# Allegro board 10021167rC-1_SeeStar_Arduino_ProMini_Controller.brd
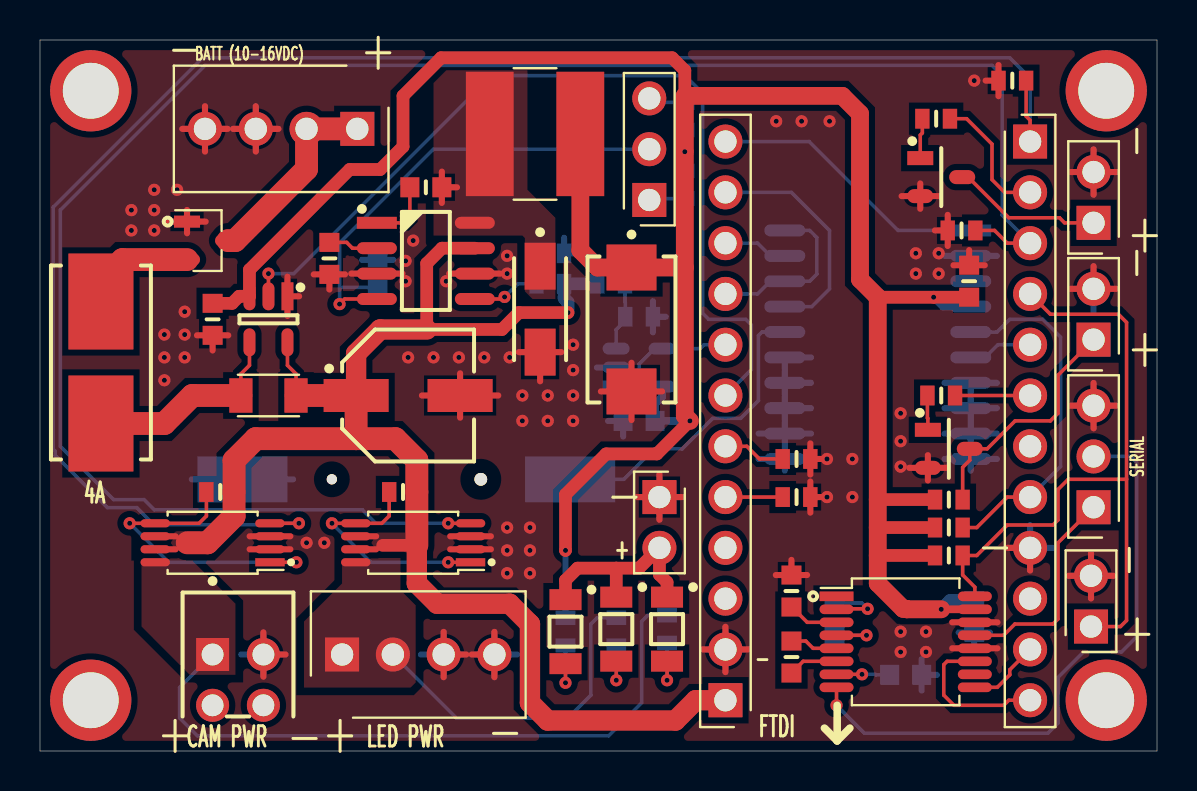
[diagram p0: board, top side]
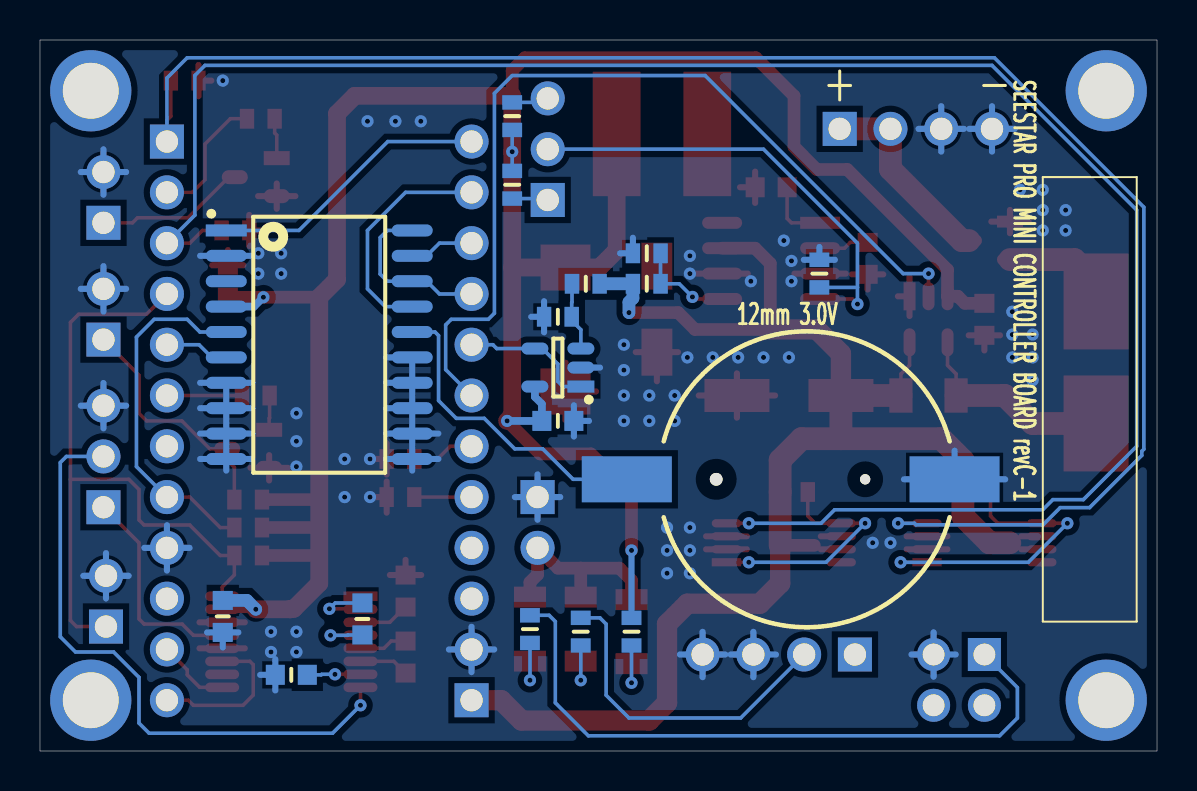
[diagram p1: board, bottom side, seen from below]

Outline 55.88 x 35.56 mm; copper layers: TOP, BOTTOM. Coordinates in mm from the lower left corner of the outline.
Outline path: 0,35.56 0,0 55.88,0 55.88,35.56 0,35.56

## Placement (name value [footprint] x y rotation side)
BT1  S8411-45R  [HARWIN_S8411-45R]  18.33 13.59 270 bottom
C1  0.1uF  [CAPC1608X90N]  19.3 28.19 0 top
C2  47uF  [CAPAE660X800N]  18.41 17.78 0 top
C3  68uF  [CAPMP7343X310N]  29.59 21.08 270 top
C4  0.10uF  [CAPC1608X87N]  8.64 21.59 270 top
C5  0.1uF  [CAPC1608X90N]  14.48 24.64 270 top
C6  0.22uF  [CAPC1608X95N]  46.74 6.73 270 bottom
C7  1.0uF  [CAPC1608X90N]  37.59 4.7 270 top
C8  0.22uF  [CAPC1608X95N]  39.75 6.6 270 bottom
C9  1.0uF  [CAPC1608X90N]  43.31 3.81 0 bottom
C10  1.0uF  [CAPC1608X90N]  37.59 8 90 top
C11  0.10uF  [CAPC1608X87N]  46.48 23.5 90 top
C12  0.10uF  [CAPC1608X87N]  29.97 16.51 180 bottom
D1  B340A-13-F  [DIOM5226X230N]  25.02 22.1 270 top
D2  LTST-C150TBKT  [LED_LTST-C150XXX]  31.37 6.1 270 top
D3  LTST-C150KRKT  [LED_LTST-C150XXX]  28.83 6.1 270 top
D4  LTST-C150KGKT  [LED_LTST-C150XXX]  26.29 5.97 270 top
F1  0154004.DRT  [FUSM9750X381N]  3.05 19.43 270 top
J1  1725672  [PHOENIX_1725672]  12.06 31.11 180 top
J2  TSW-103-14-T-S  [SAMTEC_TSW-103-14]  30.48 27.56 90 top
J3  1725656  [PHOENIX_1725656]  8.64 4.83 0 top
J4  TSW-102-14-T-S  [SAMTEC_TSW-102-14]  52.58 6.22 90 top
J5  SSW-103-01-T-S  [SAMTEC_SSW-103-XX-XXX-S-X]  52.7 14.73 90 top
J6  SSW-112-01-T-S  [SAMTEC_SSW-112-XX-XXX-S-X]  34.29 16.51 90 top
J7  SSW-112-01-T-S  [SAMTEC_SSW-112-XX-XXX-S-X]  49.53 16.51 270 top
J8  1725672  [PHOENIX_1725672]  18.92 4.83 0 top
J9  TSW-102-14-T-S  [SAMTEC_TSW-102-14]  30.99 12.7 270 top
J10  SSW-102-01-T-S  [SAMTEC_SSW-102-XX-XXX-S-X]  52.7 27.69 90 top
J11  SSW-102-01-T-S  [SAMTEC_SSW-102-XX-XXX-S-X]  52.7 21.84 90 top
L1  100uH  [IND_SRN6045]  24.77 30.86 0 top
NOREF  -  [unnamed]  2.54 33.02 0 top
NOREF#2  -  [#2]  0 0 0 top
NOREF#3  -  [#2]  0 0 0 top
NOREF#4  -  [#2]  50.8 33.02 180 top
NOREF#5  -  [#2]  -50.8 -76.2 0 top
NOREF#6  -  [#2]  0 0 0 top
NOREF#7  -  [unnamed]  2.54 2.54 0 top
NOREF#8  -  [#2]  55.88 0 90 top
NOREF#9  -  [#2]  55.88 0 90 top
NOREF#10  -  [#2]  55.88 0 90 top
NOREF#11  -  [unnamed]  53.34 33.02 0 top
NOREF#12  -  [unnamed]  53.34 2.54 0 top
NOREF#13  -  [#2]  249.81 111.38 0 top
Q1  SI2369DS-T1-GE3  [SOT95P237X112-3L20N_132]  8.38 25.53 270 top
Q2  SI6562CDQ-T1-GE3  [SOP65P640X120-8L30N]  8.64 10.41 90 top
Q3  SI6562CDQ-T1-GE3  [SOP65P640X120-8L30N]  18.67 10.41 90 top
Q4  MMBT3904  [SOT95P240X130-3N_132]  45.09 28.7 0 top
Q5  MMBT3904  [SOT95P240X130-3N_132]  45.47 15.11 0 top
R1  0.02  [RESC3015X65N]  11.43 17.78 0 top
R2  1.00M  [RESC1608X50N]  25.53 23.37 180 bottom
R3  121.0K  [RESC1608X50N]  28.57 23.37 0 bottom
R4  22.6K  [RESC1608X50N]  32.26 31.75 90 bottom
R5  41.2K  [RESC1608X50N]  32.26 28.32 270 bottom
R6  28.0K  [RESC1608X50N]  29.97 21.72 0 bottom
R7  383.0K  [RESC1608X50N]  25.53 24.89 0 bottom
R8  13.3K  [RESC1608X50N]  16.89 23.88 90 bottom
R9  100.0K  [RESC1608X50N]  9.02 12.95 0 top
R10  100.0K  [RESC1608X50N]  45.47 9.78 0 top
R11  100.0K  [RESC1608X50N]  48.64 33.53 180 top
R12  100.0K  [RESC1608X50N]  18.16 12.95 0 top
R13  100.0K  [RESC1608X50N]  46.1 26.04 180 top
R14  1.69K  [RESC1608X50N]  31.37 6.1 270 bottom
R15  1.69K  [RESC1608X50N]  28.83 5.97 270 bottom
R16  130  [RESC1608X50N]  26.29 5.97 270 bottom
R17  10.0K  [RESC1608X50N]  44.83 31.62 180 top
R18  100.0K  [RESC1608X50N]  45.47 11.18 0 top
R19  100.0K  [RESC1608X50N]  45.47 12.57 0 top
R20  0.0  [RESC1608X50N]  37.85 12.7 0 top
R21  0.0  [RESC1608X50N]  37.85 14.61 0 top
R22  10.0K  [RESC1608X50N]  45.09 17.78 180 top
U1  MAX5035DASA+  [SOIC127P600X175-8N]  19.3 24.51 0 top
U2  MAX4372FEUK+T  [SOT95P280X145-5N]  11.43 21.59 270 top
U3  AD8603AUJZ  [SOT95P280X100-5N]  29.97 19.18 0 bottom
U4  MAX3227EAAE+  [SOP65P777X199-16L32N]  43.31 5.46 270 top
U5  DS3234S#  [SOIC127P1032X265-20N]  41.91 20.32 180 bottom

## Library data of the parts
BT1 = BATTERY
C1 C4-C12 = CAP
C2 C3 = CAP_P
D1 = DIODE_SCHOTTKY
D2-D4 = LED
F1 = FUSEHOLDER_2T_2PIN
J1 J8 = CON4
J2 = HEADER 3_SYM-MOD1
J3 J10 J11 = CON2
J4 J9 = HEADER 2_SYM-MOD1
J5 = CON3
J6 J7 = CON12
L1 = IND
Q1 = MOSFET_I_EP_GSD
Q2 Q3 = MOSFET_I_PN_DSSGGSSD_SYM-MOD1
Q4 Q5 = BJT_NPN_BEC
R1-R22 = RES
U1 = MAX5035
U2 = MAX4372xEUK-T_SYM-MOD1
U3 = AD8603
U4 = MAX3227E
U5 = DS3234Sx

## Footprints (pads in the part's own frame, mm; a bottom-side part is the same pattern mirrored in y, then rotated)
CAPAE660X800N
  rect 3.251x1.651 smd: 1(-2.601,0) 2(2.601,0)
CAPC1608X87N
  rect 0.95x1.001 smd: 1(-0.8,0) 2(0.8,0)
CAPC1608X90N
  rect 0.95x1.001 smd: 1(-0.8,0) 2(0.8,0)
CAPC1608X95N
  rect 0.95x1.001 smd: 1(-0.8,0) 2(0.8,0)
CAPMP7343X310N
  rect 2.301x2.499 smd: 1(-3.099,0) 2(3.099,0)
DIOM5226X230N
  rect 2.349x1.549 smd: A(2.149,0) C(-2.149,0)
FUSM9750X381N
  rect 4.801x3.251 smd: 1(-3.051,0) 2(3.051,0)
HARWIN_S8411-45R
  round 0.635 hole 1.27 unplated: (0,-3.726)
  round 0.508 hole 1.016 unplated: (0,3.726)
  rect 2.301x4.501 smd: 1(0,-8.199) 2(0,8.199)
IND_SRN6045
  rect 2.39x6.22 smd: 1(-2.266,0) 2(2.266,0)
LED_LTST-C150XXX
  rect 1.049x1.6 smd: A(1.6,0) C(-1.6,0)
PHOENIX_1725656
  round 1.651 hole 1.092: (0,-2.54) (2.54,-2.54) 2(2.54,0)
  rect 1.651x1.651 hole 1.092: 1(0,0)
PHOENIX_1725672
  rect 1.702x1.702 hole 1.118: 1(-3.81,0)
  round 1.702 hole 1.118: 2(-1.27,0) 3(1.27,0) 4(3.81,0)
RESC1608X50N
  rect 0.719x0.991 smd: 1(-0.691,0) 2(0.691,0)
RESC3015X65N
  rect 1.161x1.72 smd: 1(-1.379,0) 2(1.379,0)
SAMTEC_SSW-102-XX-XXX-S-X
  rect 1.702x1.702 hole 1.118: 1(-1.27,0)
  round 1.702 hole 1.118: 2(1.27,0)
SAMTEC_SSW-103-XX-XXX-S-X
  rect 1.702x1.702 hole 1.118: 1(-2.54,0)
  round 1.702 hole 1.118: 2(0,0) 3(2.54,0)
SAMTEC_SSW-112-XX-XXX-S-X
  rect 1.702x1.702 hole 1.118: 1(-13.97,0)
  round 1.702 hole 1.118: 2(-11.43,0) 3(-8.89,0) 4(-6.35,0) 5(-3.81,0) 6(-1.27,0) 7(1.27,0) 8(3.81,0) 9(6.35,0) 10(8.89,0) 11(11.43,0) 12(13.97,0)
SAMTEC_TSW-102-14
  rect 1.702x1.702 hole 1.118: 1(0,0)
  round 1.702 hole 1.118: 2(2.54,0)
SAMTEC_TSW-103-14
  rect 1.702x1.702 hole 1.118: 1(0,0)
  round 1.702 hole 1.118: 2(2.54,0) 3(5.08,0)
SOIC127P600X175-8N
  rect 1.999x0.599 smd: 1(-2.451,1.905)
  oval 1.999x0.599 smd: 2(-2.451,0.635) 3(-2.451,-0.635) 4(-2.451,-1.905) 5(2.451,-1.905) 6(2.451,-0.635) 7(2.451,0.635) 8(2.451,1.905)
SOIC127P1032X265-20N
  rect 2.05x0.599 smd: 1(-4.651,5.715)
  oval 2.05x0.599 smd: 2(-4.651,4.445) 3(-4.651,3.175) 4(-4.651,1.905) 5(-4.651,0.635) 6(-4.651,-0.635) 7(-4.651,-1.905) 8(-4.651,-3.175) 9(-4.651,-4.445) 10(-4.651,-5.715) 11(4.651,-5.715) 12(4.651,-4.445) 13(4.651,-3.175) 14(4.651,-1.905) 15(4.651,-0.635) 16(4.651,0.635) 17(4.651,1.905) 18(4.651,3.175) 19(4.651,4.445) 20(4.651,5.715)
SOP65P640X120-8L30N
  rect 0.409x1.471 smd: 1(-0.975,-2.87)
  oval 0.409x1.471 smd: 2(-0.325,-2.87) 3(0.325,-2.87) 4(0.975,-2.87) 5(0.975,2.87) 6(0.325,2.87) 7(-0.325,2.87) 8(-0.975,2.87)
SOP65P777X199-16L32N
  rect 0.48x1.699 smd: 1(-2.276,-3.459)
  oval 0.48x1.699 smd: 2(-1.626,-3.459) 3(-0.975,-3.459) 4(-0.325,-3.459) 5(0.325,-3.459) 6(0.975,-3.459) 7(1.626,-3.459) 8(2.276,-3.459) 9(2.276,3.459) 10(1.626,3.459) 11(0.975,3.459) 12(0.325,3.459) 13(-0.325,3.459) 14(-0.975,3.459) 15(-1.626,3.459) 16(-2.276,3.459)
SOT95P237X112-3L20N_132
  rect 0.599x1.3 smd: 1(-0.95,-1.026)
  oval 0.599x1.3 smd: 2(0.95,-1.026) 3(0,1.026)
SOT95P240X130-3N_132
  rect 1.3x0.701 smd: 1(-1.049,0.95)
  oval 1.3x0.701 smd: 2(-1.049,-0.95) 3(1.049,0)
SOT95P280X100-5N
  rect 1.349x0.599 smd: 1(-1.151,0.95)
  oval 1.349x0.599 smd: 2(-1.151,0) 3(-1.151,-0.95) 4(1.151,-0.95) 5(1.151,0.95)
SOT95P280X145-5N
  rect 1.4x0.599 smd: 1(-1.151,0.95)
  oval 1.4x0.599 smd: 2(-1.151,0) 3(-1.151,-0.95) 4(1.151,-0.95) 5(1.151,0.95)
unnamed
  round 4.064 hole 2.794: (0,0)

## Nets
GND_SIGNAL: BT1.2(-) C2.2 C3.2 C4.2 C5.2 C6.2 C9.2 C10.2 C11.2 C12.2 D1.A J1.3 J1.4 J3.2 J4.2 J5.3 J6.2 J7.9 J8.3 J8.4 J9.1 J10.2 J11.2 Q1.1(G) Q2.2(S1B) Q2.3(S1A) Q3.2(S1B) Q3.3(S1A) Q4.2(E) Q5.2(E) R6.2 R7.2 R8.2 R11.2 R13.2 R20.2 R21.2 U1.3(SGND) U1.6(GND) U2.1(GND) U3.2(V-) U4.12(FORCEON) U4.14(GND) U5.2(NC2) U5.7(NC7) U5.8(NC8) U5.9(NC9) U5.10(NC10) U5.11(NC11) U5.12(NC12) U5.13(NC13) U5.14(NC14) U5.15(GND)
VDD: C3.1 C4.1 C6.1 C11.1 C12.1 L1.2 R4.1 R5.1 R10.1 R16.1 R18.1 R19.1 U2.3(VCC) U3.5(V+) U4.15(VCC) U5.4(VCC)
BATT: C2.1 J6.1 Q2.6(S2B) Q2.7(D2A) Q3.6(S2B) Q3.7(D2A) R1.2 R2.1 R3.1 R9.2 R12.2 U1.7(VIN) U2.5(RS-)
BATT_CURR: J6.7 U2.2(OUT)
BATT_VOLT: J6.8 U3.1(OUT) U3.4(IN-)
CAM_ON: J7.2 R17.1
CAM_POWER: J7.1 Q2.4(G1) R11.1
LED_ON: J7.6 R22.1
LED_POWER: J7.3 Q3.4(G1) R13.1
MISO: J6.10 U5.19(DOUT)
MOSI: J6.11 U5.17(DIN)
RTC_INT: J7.8 R18.2 U5.5(I\N\T\/SQW)
RTC_RESET: J7.5 U5.6(R\S\T\)
RTC_SS: J6.12 U5.1(C\S\)
RXD: J7.11 U4.9(R1_OUT)
SCK: J6.9 U5.18(SCLK_1) U5.20(SCLK_0)
TXD: J7.12 U4.11(T1_IN)
UART_SHDN: J4.1 J7.4 R10.2 U4.16(\\F\O\R\C\E\O\F\F)
N15180757: J11.1 Q5.3(C) R19.2
N15180795: Q5.1(B) R22.2
N15180973: J1.1 J1.2 Q1.3(D)
N15180993: J8.1 J8.2 Q3.8(D2) R15.1
N15181069: J6.6 R21.1
N15181133: J6.5 R20.1
N15181323: F1.1 Q1.2(S)
N15181327: F1.2 R1.1 U2.4(RS+)
N15181383: D4.A R16.2
N15181515: R3.2 R6.1 U3.3(IN+)
N15181811: J10.1 Q4.3(C)
N15181975: BT1.1(+) U5.16(VBAT)
N15182163: Q4.1(B) R17.2
N15182191: J5.1 U4.13(T1_OUT)
N15182195: J5.2 U4.8(R1_IN)
N15182295: D2.A R14.2
N15182299: D3.A R15.2
N15182387: J3.1 Q2.8(D2) R14.1
N15182531: D2.C D3.C D4.C J9.2
N15183153: R2.2 R7.1 U1.5(ON/\O\F\F\)
N15183237: C1.2 D1.C L1.1 U1.8(LX)
N15183261: J2.2 R8.1 U1.4(FB)
N15183297: C5.1 U1.2(VD)
N15183305: C1.1 U1.1(BST)
N15187989: Q3.1(D1) Q3.5(G2) R12.1
N15190814: Q2.1(D1) Q2.5(G2) R9.1
N15195894: J2.3 R4.2
N15201520: C7.2 U4.6(C2-)
N15201524: C7.1 U4.5(C2+)
N15201528: C8.2 U4.4(C1-)
N15201532: C8.1 U4.2(C1+)
N15201790: C9.1 U4.7(V-)
N15201913: C10.1 U4.3(V+)
N15224170: J2.1 R5.2

Pads without a net: J6 3 4; J7 7 10; U4 1 10; U5 3

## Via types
v1: diameter 0.61, hole 0.254, TOP to BOTTOM, 80 vias

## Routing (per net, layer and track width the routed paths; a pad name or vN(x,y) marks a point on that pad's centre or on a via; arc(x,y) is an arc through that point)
GND_SIGNAL: length 216.8
  TOP w0.305: J11.2 52.7,24.25 ; J11.2 51.57,23.11 ; J11.2 53.84,23.11 ; 8.64,20.03 C4.2 ; C4.2 9.42,20.79 ; C4.2 7.85,20.79 ; 13.7,23.84 C5.2 ; C5.2 15.26,23.84 ; C5.2 14.48,23.08 ; 22.73,3.69 J8.4 ; J8.4 21.6,4.83 ; J8.4 22.73,5.96 ; 49.53,9.03 J7.9 48.4,10.16 ; J3.2 12.28,4.83 ; J3.2 11.18,5.93 ; J3.2 11.18,3.72 ; 20.47,23.88 U1.6 23.04,23.88 ; J5.3 52.7,18.4 ; J5.3 51.57,17.27 ; J5.3 53.84,17.27 ; J5.3 52.7,16.14 ; J4.2 52.58,9.9 ; J4.2 53.71,8.76 ; J4.2 51.45,8.76 ; J4.2 52.58,7.63 ; 45.63,6.44 U4.14 47.9,6.44 ; R21.2 38.54,15.38 ; R21.2 39.18,14.61 ; R21.2 38.54,13.83 ; 8.26,31.11 8.26,32.25 ; 8.26,31.11 9.39,31.11 ; 8.26,31.11 7.12,31.11 ; 8.26,31.11 8.26,29.98 ; 12.52,10.09 Q2.2 10.49,10.09 ; J6.2 34.29,6.21 ; J6.2 34.29,3.95 ; J6.2 33.16,5.08 ; J6.2 35.42,5.08 ; 9.66,31.11 J1.3 ; J1.3 10.79,29.98 ; J1.3 11.93,31.11 ; J1.3 10.79,32.25 ; 38.54,11.92 R20.2 ; R20.2 39.18,12.7 ; R20.2 38.54,13.48 ; 36.81,8.8 C10.2 ; C10.2 37.59,9.56 ; C10.2 38.37,8.8 ; 47.9,5.14 U4.12 45.63,5.14 ; J10.2 52.7,30.09 ; J10.2 53.84,28.96 ; J10.2 52.7,27.82 ; J10.2 51.57,28.96 ; C3.2 29.59,19.42 ; C3.2 28.06,17.98 ; C3.2 29.59,16.55 ; C3.2 31.12,17.98 ; Q4.2 44.04,28.38 ; Q4.2 43.1,27.75 ; Q4.2 44.97,27.75 ; Q4.2 44.04,27.12 ; Q1.1 7.36,27.06 ; Q1.1 7.36,25.9 ; Q1.1 6.42,26.48 ; Q1.1 8.29,26.48 ; C11.2 47.26,24.3 ; C11.2 45.7,24.3 ; C11.2 46.48,25.05 ; 19.11,17.78 C2.2 ; C2.2 21.02,16.67 ; C2.2 22.92,17.78 ; C2.2 21.02,18.89 ; 44.42,13.53 Q5.2 ; Q5.2 45.35,14.16 ; Q5.2 43.48,14.16 ; Q5.2 44.42,14.8 ; R13.2 45.41,26.81 ; R13.2 45.41,25.26 ; R13.2 44.77,26.04 ; U2.1 12.96,22.74 ; U2.1 12.38,21.76 ; U2.1 12.38,23.72 ; J8.3 21.33,4.83 ; J8.3 20.19,3.69 ; J8.3 20.19,5.96 ; 25.02,18.49 D1.A ; D1.A 23.96,19.95 ; D1.A 26.08,19.95 ; 18.14,23.88 U1.3 15.57,23.88 ; 22.56,10.74 Q3.3 20.52,10.74 ; J9.1 32.12,12.7 ; J9.1 29.86,12.7 ; J9.1 30.99,13.83 ; J9.1 30.99,11.57 ; 22.56,10.09 Q3.2 20.52,10.09 ; R11.2 47.95,34.31 ; R11.2 47.95,32.75 ; R11.2 47.31,33.53 ; 10.49,10.74 Q2.3 12.52,10.74
  BOTTOM w0.305: U5.12 37.26,16.46 ; U5.12 35.95,15.88 ; U5.12 38.57,15.88 ; U5.12 37.26,15.29 ; 8.26,31.11 9.39,31.11 ; 8.26,31.11 8.26,32.25 ; 8.26,31.11 8.26,29.98 ; 8.26,31.11 7.12,31.11 ; 46.56,17.83 U5.7 ; U5.7 47.87,18.41 ; U5.7 45.25,18.41 ; 45.25,14.61 U5.10 ; U5.10 46.56,14.02 ; U5.10 46.56,15.19 ; U5.10 47.87,14.61 ; J5.3 52.7,18.4 ; J5.3 53.84,17.27 ; J5.3 52.7,16.14 ; J5.3 51.57,17.27 ; 49.53,9.03 J7.9 ; J7.9 50.66,10.16 ; J7.9 49.53,11.29 ; J7.9 48.4,10.16 ; 35.95,14.61 U5.11 ; U5.11 37.26,14.02 ; U5.11 38.57,14.61 ; U5.11 37.26,15.19 ; U5.8 47.87,17.14 ; U5.8 45.25,17.14 ; U5.8 46.56,16.56 ; U5.8 46.56,17.73 ; 34.29,3.95 J6.2 ; J6.2 33.16,5.08 ; J6.2 35.42,5.08 ; J6.2 34.29,6.21 ; J8.4 22.73,5.96 ; J8.4 23.87,4.83 ; J8.4 22.73,3.69 ; J8.4 21.6,4.83 ; C12.2 29.17,17.29 ; C12.2 29.17,15.73 ; C12.2 28.41,16.51 ; 19.06,4.83 J8.3 ; J8.3 20.19,3.69 ; J8.3 20.19,5.96 ; J8.3 21.33,4.83 ; 26.22,25.67 R7.2 26.86,24.89 ; 51.45,8.76 J4.2 ; J4.2 52.58,9.9 ; J4.2 53.71,8.76 ; J4.2 52.58,7.63 ; R6.2 30.66,22.49 ; R6.2 31.31,21.72 ; R6.2 30.66,20.94 ; 52.7,21.98 J11.2 ; J11.2 51.57,23.11 ; J11.2 52.7,24.25 ; J11.2 53.84,23.11 ; R8.2 16.89,25.21 ; R8.2 16.11,24.57 ; R8.2 17.67,24.57 ; 37.26,19.1 U5.15 38.57,19.68 ; J3.2 11.18,5.93 ; J3.2 10.07,4.83 ; J3.2 11.18,3.72 ; J3.2 12.28,4.83 ; 9.66,31.11 J1.3 ; J1.3 10.79,32.25 ; J1.3 10.79,29.98 ; J1.3 11.93,31.11 ; 46.56,15.29 U5.9 ; U5.9 45.25,15.88 ; U5.9 46.56,16.46 ; U5.9 47.87,15.88 ; 7.59,13.59 BT1.2 ; BT1.2 10.13,15.02 ; BT1.2 12.66,13.59 ; 37.26,17.83 U5.14 ; U5.14 38.57,18.41 ; U5.14 37.26,19 ; 44.11,3.03 C9.2 ; C9.2 44.11,4.59 ; C9.2 44.86,3.81 ; 52.7,27.82 J10.2 ; J10.2 52.7,30.09 ; J10.2 51.57,28.96 ; J10.2 53.84,28.96 ; 27.86,19.18 U3.2 ; U5.13 37.26,17.73 ; U5.13 37.26,16.56 ; U5.13 38.57,17.14 ; C6.2 47.52,5.93 ; C6.2 45.95,5.93 ; C6.2 46.74,5.17 ; 47.87,24.77 U5.2 45.25,24.77 ; 30.99,11.57 J9.1 ; J9.1 29.86,12.7 ; J9.1 30.99,13.83 ; J9.1 32.12,12.7
  vias: v1(4.57,27.05) v1(4.57,26.04) v1(5.71,28.07) v1(5.71,27.05) v1(5.71,26.04) v1(6.22,20.83) v1(6.22,19.68) v1(6.22,18.54) v1(6.86,28.07) v1(7.24,21.97) v1(7.24,20.83) v1(7.24,19.68) v1(13.34,10.41) v1(14.22,10.41) v1(18.29,24.51) v1(18.29,23.5) v1(18.41,19.68) v1(18.67,25.53) v1(19.68,19.68) v1(20.32,23.5) v1(20.95,19.68) v1(22.23,19.68) v1(23.37,24.77) v1(23.37,23.88) v1(23.37,11.18) v1(23.37,10.03) v1(23.37,8.89) v1(23.5,19.68) v1(24.13,17.78) v1(24.13,16.51) v1(24.51,11.18) v1(24.51,10.03) v1(24.51,8.89) v1(25.4,17.78) v1(25.4,16.51) v1(26.67,20.32) v1(26.67,19.05) v1(26.67,17.78) v1(26.67,16.51) v1(36.83,31.5) v1(38.1,31.5) v1(39.37,14.61) v1(39.37,12.7) v1(39.5,31.5) v1(40.64,14.61) v1(40.64,12.7) v1(43.05,16.89) v1(43.05,15.49) v1(43.05,14.22) v1(43.05,5.97) v1(43.05,4.95) v1(43.81,24.89) v1(43.81,23.88) v1(44.32,5.97) v1(44.32,4.95) v1(44.96,24.89) v1(44.96,23.88) v1(46.74,33.53)
VDD: length 135.3
  TOP w0.381: U4.15 v1(45.09,7.09)
  TOP w0.635: 32.26,32.77 32.26,34.04 31.62,34.67 20.07,34.67 18.16,32.77 18.16,30.23 17.02,29.08 15.49,29.08 10.48,24.07 U2.3 9.96,22.74 9.61,22.39 C4.1 ; 41.91,22.69 v1(44.7,22.69) C11.1 ; v1(32.51,16.51) 30.86,14.86 28.32,14.86 26.29,12.83 v1(26.29,10.03) ; R19.1 41.91,12.57 ; 41.91,9.78 R10.1 ; R18.1 41.91,11.18
  TOP w0.889: v1(45.09,7.09) 43.36,7.09 43.34,7.11 43.18,7.11 41.91,8.38 41.91,22.69 41.02,23.58 41.02,31.88 40.13,32.77 32.26,32.77 v1(32.26,29.97) 32.26,24.18 ; 32.26,24.18 32.26,16.76 v1(32.51,16.51) ; 32.26,24.18 C3.1 27.89,24.18 27.03,25.04 L1.2
  BOTTOM w0.178: R5.1 v1(32.26,29.97) R4.1
  BOTTOM w0.305: v1(26.29,10.03) R16.1
  BOTTOM w0.381: v1(32.51,16.51) C12.1 30.77,17.36 31.12,17.71 U3.5 ; U5.4 45.17,22.23 v1(44.7,22.69)
  BOTTOM w0.635: v1(45.09,7.09) 45.53,7.53 C6.1
BATT: length 79.4
  TOP w0.178: R1.2 12.81,18.86 12.38,19.29 U2.5
  TOP w0.305: Q2.6 6.78,10.74 ; Q3.7 16.82,10.09 ; Q3.6 16.82,10.74 ; Q2.7 6.78,10.09
  TOP w0.635: v1(26.42,21.93) 23.95,21.93 23.11,21.08 19.35,21.08 19.35,24.38 20.11,25.15 U1.7 ; 18.85,10.29 17.14,10.29
  TOP w1.016: 18.85,10.29 18.85,8.38 19.87,7.37 23.5,7.37 24.51,6.35 24.51,2.41 25.4,1.52 31.79,1.52 32.8,2.54 J6.1 ; 19.35,21.08 17.02,21.08 15.81,19.88 C2.1
  TOP w1.143: 15.81,15.62 10.79,15.62 9.71,14.54 R9.2 9.71,11.74 8.38,10.41 7.37,10.41 ; 15.81,15.62 17.78,15.62 18.85,14.55 R12.2 18.85,10.29 ; 15.81,15.62 C2.1 R1.2
  BOTTOM w0.635: v1(26.42,21.93) 26.42,22.45 26.22,22.65 R2.1 R3.1
BATT_CURR: length 45.1
  TOP w0.178: U2.2 v1(11.43,23.88)
  BOTTOM w0.178: J6.7 35.59,19.08 35.59,21.31 35.31,21.59 33.45,21.59 33.15,21.89 33.15,32.89 32.26,33.78 22.61,33.78 12.7,23.88 v1(11.43,23.88)
BATT_VOLT: length 6.8
  BOTTOM w0.178: U3.1 29.72,18.23 29.97,18.48 29.97,19.35 30.75,20.13 U3.4 33.03,20.13 33.22,20.32 J6.8
CAM_ON: length 6.6
  TOP w0.178: J7.2 48.26,27.94 47.62,28.57 47.62,30.35 46.35,31.62 R17.1
CAM_POWER: length 86.3
  TOP w0.178: R11.1 49.33,31.75 49.53,31.55 J7.1 ; v1(12.95,11.39) Q2.4
  BOTTOM w0.178: v1(12.95,11.39) 12.14,11.39 12.06,11.31 5.7,11.31 4.84,12.17 3.37,12.17 0.76,14.78 0.76,14.99 0.66,15.09 0.66,27.2 8.13,34.67 48.51,34.67 49.53,33.66 J7.1
LED_ON: length 3.8
  TOP w0.178: J7.6 R22.1
LED_POWER: length 96.2
  TOP w0.178: v1(20.42,11.39) Q3.4 ; J7.3 48.39,25.4 47.75,26.04 R13.1
  BOTTOM w0.178: J7.3 48.13,26.8 48.13,33.78 47.62,34.29 8.26,34.29 1.02,27.05 1.02,15.24 3.68,12.57 5.21,12.57 5.72,12.06 16.13,12.06 16.8,11.39 v1(20.42,11.39)
MISO: length 3.2
  BOTTOM w0.178: U5.19 36.53,24.77 35.9,25.4 J6.10
MOSI: length 11.5
  BOTTOM w0.178: U5.17 38.61,22.23 39.5,23.11 39.5,26.04 37.59,27.94 J6.11
RTC_INT: length 17.8
  TOP w0.178: R18.2 46.86,11.18 48.39,12.7 J7.8
  BOTTOM w0.178: U5.5 47.88,20.95 48.51,21.59 50.16,21.59 51.05,20.7 51.05,14.22 J7.8
RTC_RESET: length 3.2
  BOTTOM w0.178: U5.6 47.29,19.68 47.92,20.32 J7.5
RTC_SS: length 14.1
  BOTTOM w0.178: J6.12 38.48,30.48 42.93,26.04 U5.1
RXD: length 3.7
  TOP w0.178: J7.11 48.51,4.06 48.51,3.81 47.89,3.19 U4.9
SCK: length 8.6
  BOTTOM w0.178: J6.9 35.9,22.86 36.53,23.5 U5.18 38.5,23.5 38.86,23.85 38.86,25.68 38.5,26.04 U5.20
TXD: length 7.8
  TOP w0.178: U4.11 45.38,4.49 45.21,4.32 45.21,2.79 45.72,2.29 48.21,2.29 48.46,2.54 J7.12
UART_SHDN: length 35.2
  TOP w0.178: U4.16 46.77,8.2 46.16,8.81 R10.2 46.86,9.78 48.39,11.3 50.67,11.3 50.93,11.56 50.93,13.08 51.44,13.59 54.36,13.59 ; J7.4 50.55,21.84 53.95,21.84 54.36,21.44 54.36,13.59 ; 54.36,13.59 54.36,6.53 54.05,6.22 J4.1
N15180757: length 12.3
  TOP w0.178: J11.1 50.93,18.8 50.93,16.89 50.55,16.51 48.78,16.51 47.38,15.11 Q5.3 46.52,14.54 46.16,14.19 R19.2
N15180795: length 1.7
  TOP w0.178: Q5.1 44.42,16.63 44.39,16.65 R22.2
N15180973: length 10
  TOP w1.143: J1.1 13.34,31.11 13.34,29.1 9.76,25.53 Q1.3
N15180993: length 16.6
  BOTTOM w0.178: J8.2 20.83,1.65 26.42,1.65 27.56,2.79 27.56,6.35 27.87,6.66 R15.1
N15181069: length 3.1
  TOP w0.178: J6.6 35.36,15.24 35.99,14.61 R21.1
N15181133: length 2.9
  TOP w0.178: R20.1 J6.5
N15181323: length 5.8
  TOP w1.143: F1.1 3.05,23.5 4.13,24.58 Q1.2
N15181327: length 10.4
  TOP w0.178: U2.4 10.48,19.29 10.05,18.86 R1.1
  TOP w1.143: F1.2 6.22,16.38 7.62,17.78 R1.1
N15181383: length 2.8
  TOP w0.178: D4.A v1(26.29,3.41)
  BOTTOM w0.178: v1(26.29,3.41) R16.2
N15181515: length 3.4
  BOTTOM w0.178: U3.3 28.82,21.07 29.28,21.53 R6.1 29.28,22.43 29.27,22.45 R3.2
N15181811: length 7.5
  TOP w0.178: Q4.3 46.43,28.7 48.47,26.67 51,26.67 51.25,26.42 J10.1
N15181975: length 15.7
  BOTTOM w0.178: BT1.1 29.21,13.59 30.73,15.11 32.13,15.11 33.66,16.64 35.05,16.64 35.94,17.53 35.94,20.78 36.12,20.95 U5.16
N15182163: length 2
  TOP w0.178: R17.2 44.14,30.91 44.04,30.81 Q4.1
N15182191: length 10.8
  TOP w0.178: U4.13 48.2,5.79 48.77,6.35 50.67,6.35 50.93,6.6 50.93,10.41 J5.1
N15182195: length 30.8
  TOP w0.178: v1(39.85,2.29) U4.8
  BOTTOM w0.178: J5.2 54.56,14.73 54.86,14.43 54.86,5.71 54.1,4.95 52.2,4.95 50.93,3.68 50.93,1.4 50.42,0.89 41.24,0.89 v1(39.85,2.29)
N15182295: length 2.8
  TOP w0.178: v1(31.37,3.54) D2.A
  BOTTOM w0.178: R14.2 v1(31.37,3.54)
N15182299: length 2.7
  TOP w0.178: v1(28.83,3.54) D3.A
  BOTTOM w0.178: R15.2 v1(28.83,3.54)
N15182387: length 33.7
  TOP w0.178: 8.64,4.57 J3.1
  BOTTOM w0.178: J3.1 6.99,3.17 6.99,1.65 7.87,0.76 28.45,0.76 30.1,2.41 30.1,6.48 30.41,6.79 R14.1
N15182531: length 10.4
  TOP w0.635: 28.83,9.14 29.97,9.14 J9.2 30.99,8.82 31.37,8.44 D2.C ; 28.83,9.14 D3.C ; 28.83,9.14 26.89,9.14 26.29,8.54 D4.C
N15183153: length 4.9
  TOP w0.178: U1.5 23.14,22.61 v1(23.24,22.71)
  BOTTOM w0.178: R7.1 R2.2 23.9,23.37 v1(23.24,22.71)
N15183237: length 2.3
  TOP w0.305: 20.1,27.41 C1.2 ; C1.2 20.1,28.98 ; C1.2 20.86,28.19
N15183261: length 24.4
  TOP w0.178: v1(14.99,22.35) 15.24,22.61 U1.4
  BOTTOM w0.178: J2.2 19.68,30.1 14.99,25.4 14.99,23.19 ; 14.99,23.19 R8.1 ; 14.99,23.19 v1(14.99,22.35)
N15183297: length 2.5
  TOP w0.178: U1.2 15.63,25.15 15.34,25.44 C5.1
N15183305: length 3.3
  TOP w0.178: C1.1 18.5,26.63 18.29,26.42 U1.1
N15187989: length 12
  TOP w0.178: R12.1 17.47,11.76 17.1,11.39 Q3.5 v1(14.61,11.39) ; Q3.1 v1(20.42,9.44)
  BOTTOM w0.178: v1(20.42,9.44) 16.56,9.44 v1(14.61,11.39)
N15190814: length 15.7
  TOP w0.178: R9.1 8.33,11.76 7.96,11.39 Q2.5 v1(4.49,11.39) ; Q2.1 v1(12.83,9.44)
  BOTTOM w0.178: v1(12.83,9.44) 6.44,9.44 v1(4.49,11.39)
N15195894: length 1.9
  BOTTOM w0.178: J2.3 30.68,32.44 R4.2
N15201520: length 2.5
  TOP w0.178: U4.6 38.18,4.49 C7.2
N15201524: length 2.4
  TOP w0.178: C7.1 38.31,5.5 38.67,5.14 U4.5
N15201528: length 3.1
  TOP w0.178: U4.4 v1(41.35,5.79)
  BOTTOM w0.178: v1(41.35,5.79) 40.49,5.79 40.47,5.8 C8.2
N15201532: length 3.3
  TOP w0.178: v1(41.4,7.11) 39.87,7.11 U4.2
  BOTTOM w0.178: C8.1 41.11,7.4 v1(41.4,7.11)
N15201790: length 2.7
  TOP w0.178: U4.7 v1(41.12,3.84)
  BOTTOM w0.178: C9.1 41.81,3.81 41.79,3.84 v1(41.12,3.84)
N15201913: length 2.6
  TOP w0.178: U4.3 38.38,6.44 37.62,7.2 C10.1
N15224170: length 1.8
  BOTTOM w0.178: J2.1 30.55,27.63 R5.2

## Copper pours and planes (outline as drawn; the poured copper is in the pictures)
GND_SIGNAL on TOP: 0.51,35.05 55.37,35.05 55.37,0.51 0.51,0.51 ; 8 cut-outs
GND_SIGNAL on BOTTOM: 0.51,35.05 55.37,35.05 55.37,0.51 0.51,0.51 ; 11 cut-outs
BATT on TOP: 4.95,11.05 4.95,9.91 8,9.91 8,11.05
BATT on TOP: 15.11,10.92 15.11,9.91 18.8,9.91 18.8,10.92
N15180993 on TOP: 15.11,9.65 18.03,9.65 18.8,8.89 18.8,3.43 18.54,3.17 13.21,3.17 13.21,6.48 15.11,8.38
N15182387 on TOP: 5.08,9.65 7.49,9.65 9.78,7.37 9.78,3.81 7.49,3.81 5.08,6.22
N15183237 on TOP: 24.64,22.61 24.26,22.99 24.26,25.65 24.13,25.78 19.68,25.78 19.68,34.16 24.38,34.16 24.38,28.07 25.78,26.67 25.78,22.61

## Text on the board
Ref Des/Silkscreen Bottom: 12mm 3.0V | SEESTAR PRO MINI CONTROLLER BOARD revC-1 | - | +
Ref Des/Silkscreen Top: BATT (10-16VDC) | SERIAL | 4A | CAM PWR | LED PWR | + | - | FTDI
PAGE_OUTLINE: C-1 | SILK SCREEN CHANGES | -REMOVED MBARI LOGO | -INPUT VOLTAGE MAX | CHANGED TO 16V | 02/06 | APPROVED | FIGURE | SIZE | 10.0 | 43.0 | 44.0 | 110.0 | 40.0 | 50.0 | DRILL CHART: TOP to BOTTOM | ALL UNITS ARE IN MILS | PLATED | NON-PLATED | QTY | 80 | 4 | 46 | 1
